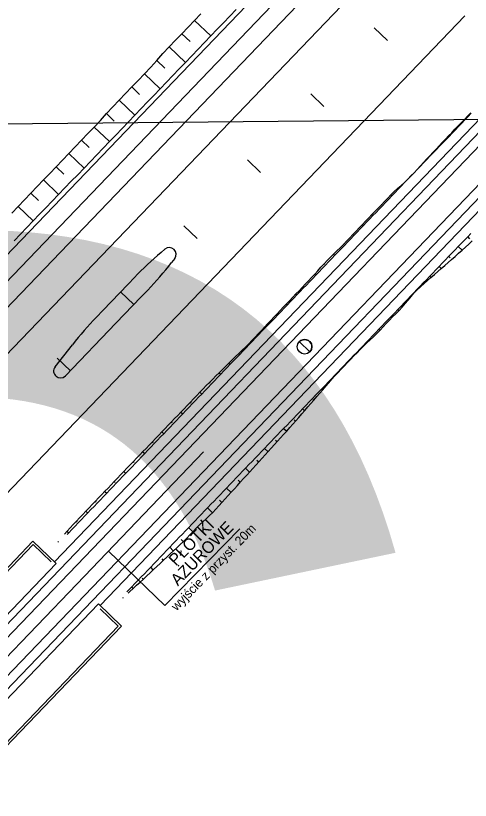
# Model space of a CAD drawing. Extents: x 6503541 to 6503743, y 5888004 to 5888145.
# Drawn here: x 6503696.406 to 6503697.598, y 5888103.34 to 5888105.397 of the extents above; entities that cross this region are included whole.
import ezdxf

# ---------------------------------------------------------------- set-up
doc = ezdxf.new("R2010")
doc.units = 0
doc.layers.add('12', color=7, linetype='Continuous')
doc.layers.add('tabela', color=7, linetype='Continuous')

msp = doc.modelspace()

# ---------------------------------------------------------------- linework, layer by layer
at = {"layer": '12'}
for p, q in [((6503695.783, 5888104.1441), (6503698.1629, 5888106.6248)), ((6503695.0784, 5888103.3403), (6503698.1975, 5888106.5915)), ((6503696.5079, 5888103.9655), (6503699.0041, 5888106.5674)), ((6503695.113, 5888103.3071), (6503698.2321, 5888106.5583)), ((6503695.2301, 5888102.5989), (6503699.0215, 5888106.5508)), ((6503695.2474, 5888102.5823), (6503699.0388, 5888106.5342)), ((6503695.1737, 5888103.2489), (6503698.2928, 5888106.5002)), ((6503695.2977, 5888102.5341), (6503699.089, 5888106.486)), ((6503695.315, 5888102.5175), (6503699.1063, 5888106.4694)), ((6503696.6274, 5888103.8508), (6503698.6205, 5888105.9283)), ((6503696.2363, 5888103.9925), (6503697.5838, 5888105.3971)), ((6503697.5746, 5888105.1161), (6503697.5739, 5888105.1167)), ((6503697.5491, 5888105.0905), (6503697.5503, 5888105.0895)), ((6503697.5249, 5888105.0639), (6503697.5244, 5888105.0644)), ((6503697.4996, 5888105.0383), (6503697.5004, 5888105.0375)), ((6503697.4337, 5888104.9685), (6503697.434, 5888104.9682)), ((6503697.4164, 5888104.9512), (6503697.4158, 5888104.9518)), ((6503697.3893, 5888104.9275), (6503697.3921, 5888104.9246)), ((6503697.3659, 5888104.9001), (6503697.3644, 5888104.9015)), ((6503697.3395, 5888104.8755), (6503697.3424, 5888104.8727)), ((6503697.316, 5888104.8481), (6503697.3146, 5888104.8495)), ((6503697.2897, 5888104.8235), (6503697.2925, 5888104.8208)), ((6503697.5968, 5888104.8123), (6503697.591, 5888104.8179)), ((6503697.2662, 5888104.7961), (6503697.2648, 5888104.7975)), ((6503697.5661, 5888104.7919), (6503697.5761, 5888104.7823)), ((6503696.7871, 5888104.7765), (6503696.7972, 5888104.7852)), ((6503697.2393, 5888104.7721), (6503697.2426, 5888104.7688)), ((6503696.8231, 5888104.7604), (6503696.8149, 5888104.7499)), ((6503697.5451, 5888104.7622), (6503697.5412, 5888104.7659)), ((6503697.2161, 5888104.7445), (6503697.2143, 5888104.7462)), ((6503697.5163, 5888104.7399), (6503697.5218, 5888104.7346)), ((6503696.7008, 5888104.6935), (6503696.7175, 5888104.7109)), ((6503697.1899, 5888104.7197), (6503697.1929, 5888104.7169)), ((6503697.493, 5888104.7124), (6503697.4914, 5888104.7139)), ((6503696.6344, 5888104.6242), (6503696.7008, 5888104.6935)), ((6503697.1666, 5888104.6922), (6503697.1652, 5888104.6935)), ((6503696.7355, 5888104.6602), (6503696.7522, 5888104.6776)), ((6503697.4573, 5888104.6779), (6503697.457, 5888104.6781)), ((6503697.4583, 5888104.6789), (6503697.458, 5888104.6791)), ((6503697.4664, 5888104.688), (6503697.4675, 5888104.6869)), ((6503696.7355, 5888104.6602), (6503696.669, 5888104.591)), ((6503697.1405, 5888104.6674), (6503697.143, 5888104.6649)), ((6503697.433, 5888104.6513), (6503697.4339, 5888104.6505)), ((6503697.1169, 5888104.6401), (6503697.1158, 5888104.6412)), ((6503696.6177, 5888104.6068), (6503696.6344, 5888104.6242)), ((6503697.0911, 5888104.615), (6503697.0932, 5888104.613)), ((6503697.41, 5888104.6236), (6503697.4072, 5888104.6262)), ((6503696.5367, 5888104.4531), (6503696.669, 5888104.591)), ((6503697.0673, 5888104.5879), (6503697.0663, 5888104.5888)), ((6503697.3837, 5888104.599), (6503697.3851, 5888104.5977)), ((6503697.3604, 5888104.5715), (6503697.3575, 5888104.5744)), ((6503697.0416, 5888104.5627), (6503697.0433, 5888104.561)), ((6503697.3334, 5888104.5477), (6503697.3341, 5888104.5469)), ((6503696.5096, 5888104.4766), (6503696.555, 5888104.5346)), ((6503697.0176, 5888104.5358), (6503697.0169, 5888104.5365)), ((6503696.9909, 5888104.5116), (6503696.9934, 5888104.509)), ((6503697.3086, 5888104.5215), (6503697.3077, 5888104.5225)), ((6503696.9668, 5888104.4847), (6503696.9651, 5888104.4865)), ((6503697.2831, 5888104.4961), (6503697.2835, 5888104.4957)), ((6503697.2584, 5888104.4699), (6503697.2578, 5888104.4705)), ((6503696.9395, 5888104.4612), (6503696.9436, 5888104.457)), ((6503697.2337, 5888104.4437), (6503697.2345, 5888104.443)), ((6503696.9163, 5888104.4335), (6503696.9139, 5888104.4359)), ((6503696.8889, 5888104.41), (6503696.8938, 5888104.4052)), ((6503697.2108, 5888104.4159), (6503697.2079, 5888104.4184)), ((6503696.8664, 5888104.3816), (6503696.8639, 5888104.384)), ((6503697.1851, 5888104.3906), (6503697.1872, 5888104.3887)), ((6503697.1636, 5888104.3616), (6503697.158, 5888104.3664)), ((6503696.839, 5888104.358), (6503696.844, 5888104.3533)), ((6503696.8166, 5888104.3297), (6503696.8141, 5888104.332)), ((6503697.1365, 5888104.3374), (6503697.1399, 5888104.3344)), ((6503696.7892, 5888104.3061), (6503696.7942, 5888104.3013)), ((6503697.1159, 5888104.3076), (6503697.1082, 5888104.3145)), ((6503696.7668, 5888104.2777), (6503696.7643, 5888104.2801)), ((6503697.0875, 5888104.2848), (6503697.0917, 5888104.2809)), ((6503697.0675, 5888104.2543), (6503697.0583, 5888104.2626)), ((6503696.5666, 5888103.9071), (6503696.8989, 5888104.2535)), ((6503696.7393, 5888104.2541), (6503696.7443, 5888104.2493)), ((6503696.7169, 5888104.2258), (6503696.7144, 5888104.2281)), ((6503697.0384, 5888104.2321), (6503697.0434, 5888104.2276)), ((6503696.6895, 5888104.2022), (6503696.6945, 5888104.1974)), ((6503697.0192, 5888104.2009), (6503697.0085, 5888104.2106)), ((6503696.6671, 5888104.1738), (6503696.6645, 5888104.1762)), ((6503696.9893, 5888104.1794), (6503696.995, 5888104.1742)), ((6503696.9708, 5888104.1476), (6503696.9586, 5888104.1586)), ((6503696.6397, 5888104.1501), (6503696.6447, 5888104.1455)), ((6503696.6173, 5888104.1217), (6503696.615, 5888104.124)), ((6503696.9402, 5888104.1268), (6503696.9466, 5888104.1209)), ((6503696.5902, 5888104.0979), (6503696.5948, 5888104.0935)), ((6503696.9224, 5888104.0943), (6503696.9093, 5888104.1072)), ((6503696.8904, 5888104.0756), (6503696.8961, 5888104.0697)), ((6503696.5676, 5888104.0696), (6503696.5654, 5888104.0718)), ((6503696.9938, 5888104.0519), (6503696.7975, 5888103.8513)), ((6503696.8708, 5888104.0442), (6503696.8595, 5888104.0553)), ((6503696.5406, 5888104.0456), (6503696.5451, 5888104.0416)), ((6503696.18, 5888103.7364), (6503696.4516, 5888104.0195)), ((6503696.1844, 5888103.7322), (6503696.4518, 5888104.011)), ((6503696.4516, 5888104.0195), (6503696.5122, 5888103.9613)), ((6503696.4518, 5888104.011), (6503696.4994, 5888103.9653)), ((6503696.5187, 5888104.017), (6503696.5171, 5888104.0184)), ((6503696.8401, 5888104.024), (6503696.8455, 5888104.0185)), ((6503696.7975, 5888103.8513), (6503696.6494, 5888103.9933)), ((6503696.8193, 5888103.9939), (6503696.81, 5888104.0037)), ((6503696.789, 5888103.9735), (6503696.793, 5888103.9693)), ((6503695.1996, 5888102.5931), (6503696.5122, 5888103.9613)), ((6503696.7667, 5888103.9447), (6503696.7601, 5888103.9517)), ((6503696.7378, 5888103.9229), (6503696.7405, 5888103.92)), ((6503695.3216, 5888102.6093), (6503696.5666, 5888103.9071)), ((6503696.7142, 5888103.8954), (6503696.7102, 5888103.8997)), ((6503696.6866, 5888103.8722), (6503696.6879, 5888103.8708)), ((6503695.3105, 5888102.4868), (6503696.6231, 5888103.855)), ((6503696.6231, 5888103.855), (6503696.6837, 5888103.7968)), ((6503696.6276, 5888103.8423), (6503696.6752, 5888103.7966)), ((6503695.4439, 5888102.5132), (6503696.6752, 5888103.7966)), ((6503695.4482, 5888102.509), (6503696.6837, 5888103.7968))]:
    msp.add_line(p, q, dxfattribs=at)
for points in [[(6503696.4025, 5888104.8072), (6503696.4191, 5888104.8245), (6503696.4357, 5888104.8418), (6503696.4524, 5888104.8592), (6503696.469, 5888104.8765), (6503696.4856, 5888104.8938), (6503696.5022, 5888104.9111), (6503696.5188, 5888104.9284), (6503696.5354, 5888104.9457), (6503696.552, 5888104.9631), (6503696.5687, 5888104.9804), (6503696.5853, 5888104.9977), (6503696.6019, 5888105.015), (6503696.6185, 5888105.0323), (6503696.6351, 5888105.0497), (6503696.6517, 5888105.067), (6503696.6684, 5888105.0843), (6503696.685, 5888105.1016), (6503696.7016, 5888105.1189), (6503696.7182, 5888105.1363), (6503696.7348, 5888105.1536), (6503696.7514, 5888105.1709), (6503696.768, 5888105.1882), (6503696.7847, 5888105.2055), (6503696.8013, 5888105.2228), (6503696.8179, 5888105.2402), (6503696.8345, 5888105.2575), (6503696.8511, 5888105.2748), (6503696.8677, 5888105.2921), (6503696.8844, 5888105.3094), (6503696.901, 5888105.3268), (6503696.9176, 5888105.3441), (6503696.9342, 5888105.3614), (6503696.9508, 5888105.3787), (6503696.9674, 5888105.396), (6503696.984, 5888105.4134)], [(6503696.3965, 5888104.8794), (6503696.4128, 5888104.8971), (6503696.4292, 5888104.9147), (6503696.4458, 5888104.932), (6503696.4625, 5888104.9492), (6503696.4791, 5888104.9665), (6503696.4958, 5888104.9838), (6503696.5124, 5888105.0011), (6503696.529, 5888105.0185), (6503696.5455, 5888105.0359), (6503696.5621, 5888105.0532), (6503696.5786, 5888105.0706), (6503696.5952, 5888105.0879), (6503696.6118, 5888105.1053), (6503696.6284, 5888105.1226), (6503696.6445, 5888105.1405), (6503696.6606, 5888105.1583), (6503696.6772, 5888105.1756), (6503696.6938, 5888105.1929), (6503696.7104, 5888105.2103), (6503696.727, 5888105.2276), (6503696.7436, 5888105.2449), (6503696.7602, 5888105.2623), (6503696.7765, 5888105.2799), (6503696.7923, 5888105.298), (6503696.8089, 5888105.3153), (6503696.8255, 5888105.3327), (6503696.8421, 5888105.35), (6503696.8587, 5888105.3673), (6503696.8753, 5888105.3847), (6503696.8918, 5888105.402)], [(6503696.8753, 5888105.3847), (6503696.9176, 5888105.3441)], [(6503696.8421, 5888105.35), (6503696.8632, 5888105.3297)], [(6503697.3804, 5888105.3325), (6503697.3457, 5888105.3657)], [(6503696.8089, 5888105.3153), (6503696.8511, 5888105.2748)], [(6503696.7765, 5888105.2799), (6503696.7972, 5888105.26)], [(6503696.7436, 5888105.2449), (6503696.7847, 5888105.2055)], [(6503696.7104, 5888105.2103), (6503696.7309, 5888105.1906)], [(6503697.2142, 5888105.1593), (6503697.1796, 5888105.1925)], [(6503696.6772, 5888105.1756), (6503696.7182, 5888105.1363)], [(6503697.4506, 5888104.9855), (6503697.4588, 5888104.9943), (6503697.4669, 5888105.0032), (6503697.4751, 5888105.012), (6503697.4832, 5888105.0208), (6503697.4914, 5888105.0295), (6503697.4997, 5888105.0383), (6503697.5079, 5888105.047), (6503697.5162, 5888105.0557), (6503697.5244, 5888105.0644), (6503697.5327, 5888105.0731), (6503697.5409, 5888105.0818), (6503697.5492, 5888105.0905), (6503697.5574, 5888105.0993), (6503697.5657, 5888105.108), (6503697.5739, 5888105.1167), (6503697.5822, 5888105.1254), (6503697.5904, 5888105.1341), (6503697.5987, 5888105.1428)], [(6503696.5409, 5888104.0373), (6503696.5451, 5888104.0417), (6503696.5534, 5888104.0503), (6503696.5617, 5888104.059), (6503696.57, 5888104.0676), (6503696.5783, 5888104.0763), (6503696.5866, 5888104.085), (6503696.5949, 5888104.0936), (6503696.6032, 5888104.1023), (6503696.6115, 5888104.1109), (6503696.6199, 5888104.1196), (6503696.6282, 5888104.1283), (6503696.6365, 5888104.1369), (6503696.6448, 5888104.1456), (6503696.6531, 5888104.1542), (6503696.6614, 5888104.1629), (6503696.6697, 5888104.1716), (6503696.678, 5888104.1802), (6503696.6863, 5888104.1889), (6503696.6946, 5888104.1975), (6503696.7029, 5888104.2062), (6503696.7112, 5888104.2149), (6503696.7195, 5888104.2235), (6503696.7278, 5888104.2322), (6503696.7362, 5888104.2408), (6503696.7445, 5888104.2495), (6503696.7528, 5888104.2582), (6503696.7611, 5888104.2668), (6503696.7694, 5888104.2755), (6503696.7777, 5888104.2841), (6503696.786, 5888104.2928), (6503696.7943, 5888104.3014), (6503696.8026, 5888104.3101), (6503696.8109, 5888104.3188), (6503696.8192, 5888104.3274), (6503696.8275, 5888104.3361), (6503696.8358, 5888104.3447), (6503696.8442, 5888104.3534), (6503696.8525, 5888104.3621), (6503696.8608, 5888104.3707), (6503696.8691, 5888104.3794), (6503696.8774, 5888104.388), (6503696.8857, 5888104.3967), (6503696.894, 5888104.4054), (6503696.9023, 5888104.414), (6503696.9106, 5888104.4227), (6503696.9189, 5888104.4313), (6503696.9272, 5888104.44), (6503696.9355, 5888104.4487), (6503696.9438, 5888104.4573), (6503696.9522, 5888104.466), (6503696.9605, 5888104.4746), (6503696.9688, 5888104.4833), (6503696.9771, 5888104.492), (6503696.9854, 5888104.5006), (6503696.9937, 5888104.5093), (6503697.002, 5888104.5179), (6503697.0103, 5888104.5266), (6503697.0186, 5888104.5353), (6503697.0269, 5888104.5439), (6503697.0352, 5888104.5526), (6503697.0435, 5888104.5612), (6503697.0518, 5888104.5699), (6503697.0601, 5888104.5786), (6503697.0685, 5888104.5872), (6503697.0768, 5888104.5959), (6503697.0851, 5888104.6045), (6503697.0934, 5888104.6132), (6503697.1017, 5888104.6218), (6503697.11, 5888104.6305), (6503697.1183, 5888104.6392), (6503697.1266, 5888104.6478), (6503697.1349, 5888104.6565), (6503697.1432, 5888104.6651), (6503697.1515, 5888104.6738), (6503697.1598, 5888104.6825), (6503697.1681, 5888104.6911), (6503697.1765, 5888104.6998), (6503697.1848, 5888104.7084), (6503697.1931, 5888104.7171), (6503697.2014, 5888104.7258), (6503697.2097, 5888104.7344), (6503697.218, 5888104.7431), (6503697.2263, 5888104.7517), (6503697.2346, 5888104.7604), (6503697.2429, 5888104.7691), (6503697.2512, 5888104.7777), (6503697.2595, 5888104.7864), (6503697.2678, 5888104.795), (6503697.2761, 5888104.8037), (6503697.2845, 5888104.8124), (6503697.2928, 5888104.821), (6503697.3011, 5888104.8297), (6503697.3094, 5888104.8383), (6503697.3177, 5888104.847), (6503697.326, 5888104.8557), (6503697.3343, 5888104.8643), (6503697.3426, 5888104.873), (6503697.3509, 5888104.8816), (6503697.3592, 5888104.8903), (6503697.3675, 5888104.8989), (6503697.3758, 5888104.9076), (6503697.3841, 5888104.9163), (6503697.3924, 5888104.9249), (6503697.4008, 5888104.9336), (6503697.4091, 5888104.9422), (6503697.4174, 5888104.9509), (6503697.4257, 5888104.9596), (6503697.434, 5888104.9682), (6503697.4423, 5888104.9769), (6503697.4506, 5888104.9855), (6503697.4589, 5888104.9942), (6503697.4672, 5888105.0029), (6503697.4755, 5888105.0115), (6503697.4838, 5888105.0202), (6503697.4921, 5888105.0288), (6503697.5004, 5888105.0375), (6503697.5088, 5888105.0462), (6503697.5171, 5888105.0548), (6503697.5254, 5888105.0635), (6503697.5337, 5888105.0721), (6503697.542, 5888105.0808), (6503697.5503, 5888105.0895), (6503697.5586, 5888105.0981), (6503697.5669, 5888105.1068), (6503697.5752, 5888105.1154), (6503697.5835, 5888105.1241), (6503697.5918, 5888105.1328), (6503697.6001, 5888105.1414)], [(6503696.6445, 5888105.1405), (6503696.6647, 5888105.121)], [(6503696.6118, 5888105.1053), (6503696.6517, 5888105.067)], [(6503696.5786, 5888105.0706), (6503696.5986, 5888105.0515)], [(6503696.5455, 5888105.0359), (6503696.5853, 5888104.9977)], [(6503697.0481, 5888104.9861), (6503697.0134, 5888105.0193)], [(6503696.5124, 5888105.0011), (6503696.5322, 5888104.9821)], [(6503697.4337, 5888104.9685), (6503697.4421, 5888104.977), (6503697.4506, 5888104.9855)], [(6503696.4791, 5888104.9665), (6503696.5188, 5888104.9284)], [(6503696.5343, 5888104.0383), (6503696.5408, 5888104.0458), (6503696.549, 5888104.0545), (6503696.5573, 5888104.0632), (6503696.5655, 5888104.0719), (6503696.5738, 5888104.0806), (6503696.5821, 5888104.0893), (6503696.5903, 5888104.098), (6503696.5986, 5888104.1067), (6503696.6068, 5888104.1154), (6503696.6151, 5888104.1242), (6503696.6234, 5888104.1329), (6503696.6316, 5888104.1416), (6503696.6399, 5888104.1503), (6503696.6482, 5888104.159), (6503696.6564, 5888104.1677), (6503696.6647, 5888104.1764), (6503696.673, 5888104.185), (6503696.6813, 5888104.1937), (6503696.6896, 5888104.2023), (6503696.6979, 5888104.211), (6503696.7062, 5888104.2196), (6503696.7146, 5888104.2283), (6503696.7229, 5888104.237), (6503696.7312, 5888104.2456), (6503696.7395, 5888104.2543), (6503696.7478, 5888104.2629), (6503696.7561, 5888104.2716), (6503696.7644, 5888104.2802), (6503696.7727, 5888104.2889), (6503696.781, 5888104.2975), (6503696.7894, 5888104.3062), (6503696.7977, 5888104.3149), (6503696.806, 5888104.3235), (6503696.8143, 5888104.3322), (6503696.8226, 5888104.3409), (6503696.8309, 5888104.3495), (6503696.8392, 5888104.3582), (6503696.8475, 5888104.3668), (6503696.8558, 5888104.3755), (6503696.8641, 5888104.3842), (6503696.8724, 5888104.3928), (6503696.8807, 5888104.4015), (6503696.889, 5888104.4102), (6503696.8973, 5888104.4188), (6503696.9056, 5888104.4275), (6503696.914, 5888104.436), (6503696.9226, 5888104.4445), (6503696.9311, 5888104.4529), (6503696.9397, 5888104.4613), (6503696.9482, 5888104.4698), (6503696.9567, 5888104.4782), (6503696.9653, 5888104.4866), (6503696.9738, 5888104.4951), (6503696.9824, 5888104.5035), (6503696.9911, 5888104.5117), (6503696.9998, 5888104.52), (6503697.0085, 5888104.5283), (6503697.0171, 5888104.5367), (6503697.0253, 5888104.5454), (6503697.0336, 5888104.5541), (6503697.0418, 5888104.5629), (6503697.0501, 5888104.5716), (6503697.0583, 5888104.5803), (6503697.0665, 5888104.5891), (6503697.0748, 5888104.5978), (6503697.083, 5888104.6065), (6503697.0913, 5888104.6152), (6503697.0995, 5888104.624), (6503697.1077, 5888104.6327), (6503697.116, 5888104.6414), (6503697.1242, 5888104.6501), (6503697.1324, 5888104.6589), (6503697.1407, 5888104.6676), (6503697.1489, 5888104.6763), (6503697.1572, 5888104.685), (6503697.1654, 5888104.6938), (6503697.1736, 5888104.7025), (6503697.1819, 5888104.7112), (6503697.1901, 5888104.7199), (6503697.1984, 5888104.7287), (6503697.2064, 5888104.7375), (6503697.2145, 5888104.7464), (6503697.2227, 5888104.7552), (6503697.2309, 5888104.7639), (6503697.2395, 5888104.7723), (6503697.2482, 5888104.7806), (6503697.2568, 5888104.789), (6503697.2651, 5888104.7977), (6503697.2734, 5888104.8064), (6503697.2817, 5888104.815), (6503697.29, 5888104.8237), (6503697.2983, 5888104.8324), (6503697.3066, 5888104.841), (6503697.3149, 5888104.8497), (6503697.3232, 5888104.8584), (6503697.3315, 5888104.867), (6503697.3398, 5888104.8757), (6503697.348, 5888104.8844), (6503697.3563, 5888104.893), (6503697.3646, 5888104.9017), (6503697.3729, 5888104.9104), (6503697.3812, 5888104.919), (6503697.3895, 5888104.9277), (6503697.3981, 5888104.9362), (6503697.4071, 5888104.9441), (6503697.4162, 5888104.9521), (6503697.4252, 5888104.96), (6503697.4337, 5888104.9685)], [(6503696.4458, 5888104.932), (6503696.4657, 5888104.9129)], [(6503696.4128, 5888104.8971), (6503696.4524, 5888104.8592)], [(6503696.8819, 5888104.8129), (6503696.8473, 5888104.8461)], [(6503696.6978, 5888103.8868), (6503696.702, 5888103.8911), (6503696.7103, 5888103.8998), (6503696.7186, 5888103.9085), (6503696.7269, 5888103.9171), (6503696.7352, 5888103.9258), (6503696.7435, 5888103.9344), (6503696.7518, 5888103.9431), (6503696.7601, 5888103.9518), (6503696.7684, 5888103.9604), (6503696.7768, 5888103.9691), (6503696.7851, 5888103.9777), (6503696.7934, 5888103.9864), (6503696.8017, 5888103.9951), (6503696.81, 5888104.0037), (6503696.8183, 5888104.0124), (6503696.8266, 5888104.021), (6503696.8349, 5888104.0297), (6503696.8432, 5888104.0383), (6503696.8515, 5888104.047), (6503696.8598, 5888104.0557), (6503696.8681, 5888104.0643), (6503696.8764, 5888104.073), (6503696.8848, 5888104.0816), (6503696.8931, 5888104.0903), (6503696.9014, 5888104.099), (6503696.9097, 5888104.1076), (6503696.918, 5888104.1163), (6503696.9263, 5888104.1249), (6503696.9346, 5888104.1336), (6503696.9429, 5888104.1423), (6503696.9512, 5888104.1509), (6503696.9595, 5888104.1596), (6503696.9678, 5888104.1682), (6503696.9761, 5888104.1769), (6503696.9844, 5888104.1856), (6503696.9927, 5888104.1942), (6503697.0011, 5888104.2029), (6503697.0094, 5888104.2115), (6503697.0177, 5888104.2202), (6503697.026, 5888104.2289), (6503697.0343, 5888104.2375), (6503697.0426, 5888104.2462), (6503697.0509, 5888104.2548), (6503697.0592, 5888104.2635), (6503697.0675, 5888104.2722), (6503697.0758, 5888104.2808), (6503697.0841, 5888104.2895), (6503697.0924, 5888104.2981), (6503697.1007, 5888104.3068), (6503697.1091, 5888104.3155), (6503697.1174, 5888104.3241), (6503697.1257, 5888104.3328), (6503697.134, 5888104.3414), (6503697.1423, 5888104.3501), (6503697.1506, 5888104.3587), (6503697.1589, 5888104.3674), (6503697.1672, 5888104.3761), (6503697.1755, 5888104.3847), (6503697.1838, 5888104.3934), (6503697.1921, 5888104.402), (6503697.2004, 5888104.4107), (6503697.2087, 5888104.4194), (6503697.2171, 5888104.428), (6503697.2254, 5888104.4367), (6503697.2337, 5888104.4453), (6503697.242, 5888104.454), (6503697.2503, 5888104.4627), (6503697.2586, 5888104.4713), (6503697.2669, 5888104.48), (6503697.2752, 5888104.4886), (6503697.2835, 5888104.4973), (6503697.2918, 5888104.506), (6503697.3001, 5888104.5146), (6503697.3084, 5888104.5233), (6503697.3167, 5888104.5319), (6503697.3251, 5888104.5406), (6503697.3334, 5888104.5493), (6503697.3417, 5888104.5579), (6503697.35, 5888104.5666), (6503697.3583, 5888104.5752), (6503697.3666, 5888104.5839), (6503697.3749, 5888104.5926), (6503697.3832, 5888104.6012), (6503697.3915, 5888104.6099), (6503697.3998, 5888104.6185), (6503697.4081, 5888104.6272), (6503697.4164, 5888104.6358), (6503697.4247, 5888104.6445), (6503697.433, 5888104.6532), (6503697.4414, 5888104.6618), (6503697.4497, 5888104.6705), (6503697.458, 5888104.6791), (6503697.4663, 5888104.6878), (6503697.4746, 5888104.6965), (6503697.4829, 5888104.7051), (6503697.4912, 5888104.7138), (6503697.4995, 5888104.7224), (6503697.5078, 5888104.7311), (6503697.5161, 5888104.7398), (6503697.5244, 5888104.7484), (6503697.5327, 5888104.7571), (6503697.541, 5888104.7657), (6503697.5494, 5888104.7744), (6503697.5577, 5888104.7831), (6503697.566, 5888104.7917), (6503697.5743, 5888104.8004), (6503697.5826, 5888104.809), (6503697.5909, 5888104.8177), (6503697.5992, 5888104.8264)], [(6503697.4583, 5888104.6789), (6503697.4673, 5888104.6868), (6503697.4764, 5888104.6947), (6503697.4854, 5888104.7027), (6503697.4945, 5888104.7106), (6503697.5035, 5888104.7186), (6503697.5126, 5888104.7265), (6503697.5216, 5888104.7345), (6503697.5307, 5888104.7424), (6503697.5398, 5888104.7503), (6503697.5488, 5888104.7583), (6503697.5579, 5888104.7662), (6503697.5669, 5888104.7742), (6503697.576, 5888104.7821), (6503697.585, 5888104.7901), (6503697.5941, 5888104.798), (6503697.6025, 5888104.8066)], [(6503696.7158, 5888104.6397), (6503696.6811, 5888104.6729)], [(6503696.7014, 5888103.8834), (6503696.7058, 5888103.8875), (6503696.7145, 5888103.8957), (6503696.7233, 5888103.904), (6503696.7321, 5888103.9122), (6503696.7408, 5888103.9204), (6503696.7496, 5888103.9286), (6503696.7584, 5888103.9368), (6503696.7671, 5888103.945), (6503696.7759, 5888103.9533), (6503696.7847, 5888103.9615), (6503696.7934, 5888103.9697), (6503696.8022, 5888103.9779), (6503696.811, 5888103.9861), (6503696.8198, 5888103.9943), (6503696.8285, 5888104.0026), (6503696.8373, 5888104.0108), (6503696.8461, 5888104.019), (6503696.8548, 5888104.0272), (6503696.863, 5888104.036), (6503696.8713, 5888104.0447), (6503696.8795, 5888104.0534), (6503696.8878, 5888104.0621), (6503696.8966, 5888104.0702), (6503696.9055, 5888104.0784), (6503696.9143, 5888104.0866), (6503696.923, 5888104.0948), (6503696.9311, 5888104.1037), (6503696.9391, 5888104.1126), (6503696.9472, 5888104.1215), (6503696.9553, 5888104.1304), (6503696.9633, 5888104.1393), (6503696.9714, 5888104.1482), (6503696.9794, 5888104.1571), (6503696.9875, 5888104.166), (6503696.9956, 5888104.1749), (6503697.0036, 5888104.1838), (6503697.0117, 5888104.1927), (6503697.0198, 5888104.2016), (6503697.0278, 5888104.2105), (6503697.0359, 5888104.2193), (6503697.044, 5888104.2282), (6503697.052, 5888104.2371), (6503697.0601, 5888104.246), (6503697.0681, 5888104.2549), (6503697.0762, 5888104.2638), (6503697.0843, 5888104.2727), (6503697.0923, 5888104.2816), (6503697.1004, 5888104.2905), (6503697.1085, 5888104.2994), (6503697.1165, 5888104.3083), (6503697.1246, 5888104.3172), (6503697.1327, 5888104.3261), (6503697.1405, 5888104.3351), (6503697.1484, 5888104.3442), (6503697.1563, 5888104.3533), (6503697.1642, 5888104.3623), (6503697.1721, 5888104.3714), (6503697.18, 5888104.3804), (6503697.1879, 5888104.3895), (6503697.1958, 5888104.3986), (6503697.2037, 5888104.4076), (6503697.2115, 5888104.4167), (6503697.2194, 5888104.4257), (6503697.2273, 5888104.4348), (6503697.2352, 5888104.4439), (6503697.2431, 5888104.4529), (6503697.251, 5888104.462), (6503697.2592, 5888104.4707), (6503697.2676, 5888104.4793), (6503697.2759, 5888104.4879), (6503697.2843, 5888104.4965), (6503697.2927, 5888104.5051), (6503697.3011, 5888104.5137), (6503697.3094, 5888104.5223), (6503697.3178, 5888104.5309), (6503697.3262, 5888104.5395), (6503697.335, 5888104.5477), (6503697.3441, 5888104.5556), (6503697.3529, 5888104.5637), (6503697.3613, 5888104.5724), (6503697.3693, 5888104.5813), (6503697.3776, 5888104.5899), (6503697.3859, 5888104.5986), (6503697.3942, 5888104.6073), (6503697.4026, 5888104.6159), (6503697.4109, 5888104.6246), (6503697.4192, 5888104.6332), (6503697.4271, 5888104.6423), (6503697.4347, 5888104.6515), (6503697.4424, 5888104.6608), (6503697.4501, 5888104.6701), (6503697.4583, 5888104.6789)], [(6503697.1497, 5888104.5426), (6503697.1774, 5888104.516)], [(6503696.5496, 5888104.4665), (6503696.515, 5888104.4997)]]:
    msp.add_lwpolyline(points, dxfattribs=at)
msp.add_circle((6503697.1635, 5888104.5293), 0.0192, dxfattribs=at)
for centre, radius, start, end in [((6503697.4103, 5888104.0463), 0.96, 130.4775, 136.1881), ((6503696.8089, 5888104.7715), 0.018, 321.8987, 130.4775), ((6503696.0594, 5888105.3422), 0.96, 316.1881, 321.8987), ((6503697.3104, 5888103.9422), 0.96, 136.1881, 141.8987), ((6503697.1635, 5888104.5293), 0.0192, 11.7409, 136.1881), ((6503697.1635, 5888104.5293), 0.0192, 316.1881, 11.7409), ((6503696.5237, 5888104.4655), 0.018, 141.8987, 316.1881)]:
    msp.add_arc(centre, radius, start, end, dxfattribs=at)
at = {"layer": 'tabela'}
msp.add_line((6503691.6249, 5888105.0696), (6503698.8603, 5888105.1372), dxfattribs=at)
msp.add_line((6503691.6249, 5888105.0696), (6503698.8603, 5888105.1372), dxfattribs=at)

# ---------------------------------------------------------------- texts
at = {"layer": '12'}
for s, height, rotation, p in [('16', 4.22297, 0.7393, (6503691.5209, 5888100.4873)), ('PŁOTKI', 0.0311, 45.7134, (6503696.8261, 5888103.9529)), ('AŻUROWE', 0.0311, 45.7134, (6503696.8313, 5888103.9006)), ('wyjście z przyst. 20m', 0.023802, 45.7134, (6503696.828, 5888103.8355))]:
    msp.add_text(s, height=height, rotation=rotation, dxfattribs=at).set_placement(p)

doc.saveas('drawing.dxf')
